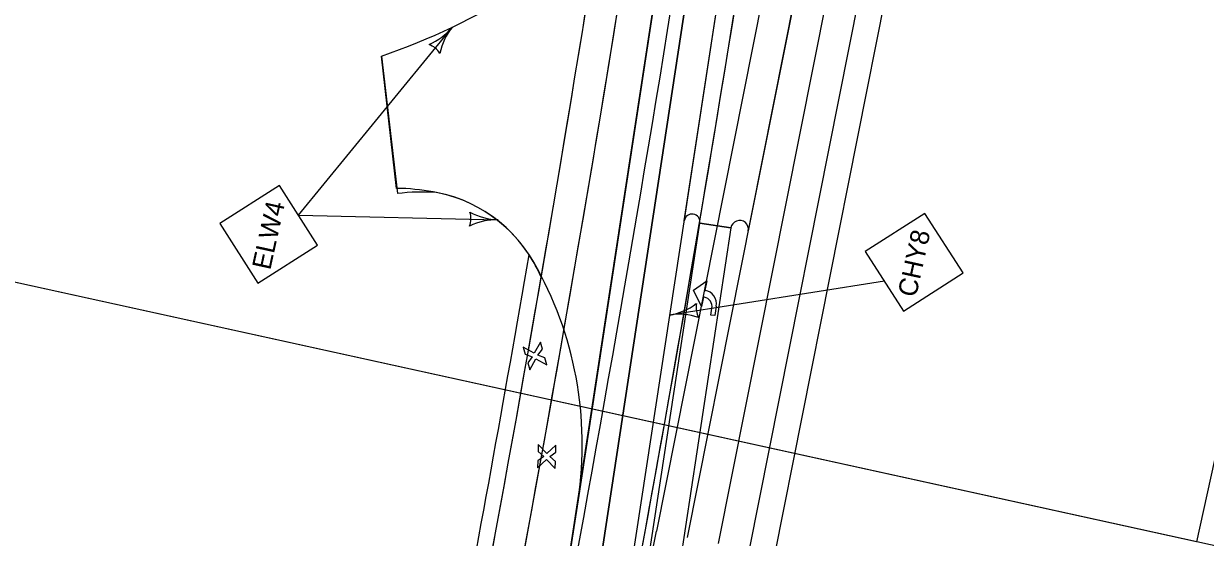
# Model space of a CAD drawing. Extents: x 14104283 to 14128447, y 8633203 to 8671666.
# Drawn here: x 14107697.3 to 14108147.9, y 8639738.3 to 8639934.4 of the extents above; entities that cross this region are included whole.
import ezdxf

# ---------------------------------------------------------------- set-up
doc = ezdxf.new("R2010")
doc.units = 0
for name, color, linetype in [('Cell', 7, 'Continuous'), ('Default', 7, 'Continuous'), ('dsnNonPlotable', 7, 'Continuous'), ('dsnPaintPlaceBrokenLineWhite', 7, 'Continuous'), ('dsnPaintPlaceEdgeLineRightWhite', 7, 'Continuous'), ('dsnStdLabel', 7, 'Continuous'), ('dsnStgShadingPrevPav', 7, 'Continuous')]:
    doc.layers.add(name, color=color, linetype=linetype)

msp = doc.modelspace()

# ---------------------------------------------------------------- linework, layer by layer
at = {"layer": 'Cell'}
for p, q in [((14107957.11, 8639832.53), (14107957.29, 8639832.5)), ((14107956.89, 8639829.91), (14107956.58, 8639829.95)), ((14107894.33, 8639812.75), (14107892.01, 8639808.57)), ((14107895.09, 8639810.1), (14107894.33, 8639812.75)), ((14107892.01, 8639808.57), (14107887.84, 8639810.89)), ((14107887.84, 8639810.89), (14107888.6, 8639808.24)), ((14107888.6, 8639808.24), (14107891.24, 8639807.18)), ((14107893.4, 8639807.8), (14107895.09, 8639810.1)), ((14107891.24, 8639807.18), (14107889.56, 8639804.88)), ((14107889.56, 8639804.88), (14107890.32, 8639802.24)), ((14107890.32, 8639802.24), (14107892.63, 8639806.41)), ((14107892.63, 8639806.41), (14107896.81, 8639804.09)), ((14107896.05, 8639806.74), (14107893.4, 8639807.8)), ((14107896.81, 8639804.09), (14107896.05, 8639806.74)), ((14107893.54, 8639773.76), (14107893.45, 8639771.01)), ((14107896.8, 8639770.27), (14107893.54, 8639773.76)), ((14107900.29, 8639773.53), (14107896.8, 8639770.27)), ((14107900.2, 8639770.79), (14107900.29, 8639773.53)), ((14107893.24, 8639764.76), (14107896.73, 8639768.02)), ((14107895.64, 8639769.19), (14107893.33, 8639767.51)), ((14107893.45, 8639771.01), (14107895.64, 8639769.19)), ((14107896.73, 8639768.02), (14107899.99, 8639764.54)), ((14107897.89, 8639769.11), (14107900.2, 8639770.79)), ((14107900.08, 8639767.29), (14107897.89, 8639769.11)), ((14107893.33, 8639767.51), (14107893.24, 8639764.76)), ((14107899.99, 8639764.54), (14107900.08, 8639767.29))]:
    msp.add_line(p, q, dxfattribs=at)
for points in [[(14107952.78, 8639832.67), (14107957.86, 8639836.14), (14107957.11, 8639832.53)], [(14107952.78, 8639832.67), (14107957.86, 8639836.14), (14107957.11, 8639832.53)], [(14107956.58, 8639829.95), (14107955.83, 8639826.35), (14107952.78, 8639832.67)], [(14107956.58, 8639829.95), (14107955.83, 8639826.35), (14107952.78, 8639832.67)], [(14107957.11, 8639832.53), (14107957.29, 8639832.5)], [(14107956.89, 8639829.91), (14107956.58, 8639829.95)], [(14107961.41, 8639826.54), (14107960.84, 8639822.91), (14107959.37, 8639823.14), (14107959.77, 8639825.73)], [(14107961.41, 8639826.54), (14107960.84, 8639822.91), (14107959.37, 8639823.14), (14107959.77, 8639825.73)]]:
    msp.add_lwpolyline(points, dxfattribs=at)
for centre, major_axis in [((14107956.49, 8639827.31), (-0.81, -5.19)), ((14107956.49, 8639827.31), (-0.81, -5.19)), ((14107956.32, 8639826.27), (-0.57, -3.64)), ((14107956.32, 8639826.27), (-0.57, -3.64))]:
    msp.add_ellipse(centre, major_axis=major_axis, ratio=0.9474, start_param=1.570796, end_param=3.141593, dxfattribs=at)
at = {"layer": 'Default'}
for p, q in [((14107885.37, 8639599.61), (14107990.94, 8640291.61)), ((14108002.8, 8640289.8), (14107897.23, 8639597.8)), ((14108002.8, 8640289.8), (14107897.23, 8639597.8)), ((14107909.09, 8639595.99), (14108014.66, 8640287.99)), ((14108004.96, 8640013.11), (14107973.63, 8639855.23)), ((14108028.5, 8640008.43), (14107973.96, 8639733.6)), ((14107949.24, 8639859.12), (14107967.08, 8639976.1)), ((14107950.42, 8639738.27), (14107992.68, 8639951.24)), ((14107937.44, 8639940.91), (14107908.71, 8639752.63)), ((14107839.51, 8639871.5), (14107833.76, 8639922)), ((14107915.03, 8639595.09), (14107955.17, 8639858.22)), ((14107955.17, 8639858.22), (14107967.03, 8639856.41)), ((14107967.03, 8639856.41), (14107955.17, 8639858.22)), ((14107967.03, 8639856.41), (14107944.41, 8639708.12))]:
    msp.add_line(p, q, dxfattribs=at)
for centre, radius, start, end in [((14107752.7, 8640158.5), 250, 288.9195, 302.3186), ((14107838.11, 8639781.51), 90, 80.198, 89.1076), ((14107844.07, 8639816), 55, 29.809, 80.198), ((14107952.2, 8639858.67), 3, 351.326, 171.326), ((14107970.34, 8639855.88), 3.35, 348.776, 171.0218), ((14107770.31, 8639773.74), 140, 351.326, 29.809)]:
    msp.add_arc(centre, radius, start, end, dxfattribs=at)
at = {"layer": 'dsnNonPlotable'}
for points in [[(14107490.45, 8639880.3), (14107826.84, 8641411.28), (14108813.31, 8641194.53), (14108476.92, 8639663.55)], [(14107651.31, 8639844.94), (14107987.7, 8641375.92), (14108480.93, 8641267.54), (14108144.54, 8639736.56)]]:
    msp.add_lwpolyline(points, close=True, dxfattribs=at)
at = {"layer": 'dsnPaintPlaceBrokenLineWhite'}
msp.add_line((14107897.23, 8639597.8), (14108002.8, 8640289.8), dxfattribs=at)
at = {"layer": 'dsnPaintPlaceEdgeLineRightWhite'}
msp.add_line((14107908.71, 8639752.63), (14107885.37, 8639599.61), dxfattribs=at)
for centre, radius, start, end in [((14107752.7, 8640158.5), 250, 288.9195, 302.3186), ((14107838.11, 8639781.51), 90, 80.198, 89.1076), ((14107844.07, 8639816), 55, 29.809, 80.198), ((14107770.31, 8639773.74), 140, 351.326, 29.809)]:
    msp.add_arc(centre, radius, start, end, dxfattribs=at)
at = {"layer": 'dsnStdLabel'}
for p, q in [((14107802.08, 8639861.24), (14107860.8, 8639933.07)), ((14107802.08, 8639861.24), (14107878.22, 8639859.5)), ((14108025.51, 8639836.03), (14107943.57, 8639823.14))]:
    msp.add_line(p, q, dxfattribs=at)
for points in [[(14107786.61, 8639835.31), (14107809.35, 8639849.86), (14107794.8, 8639872.61), (14107772.06, 8639858.06)], [(14108032.78, 8639824.65), (14108055.53, 8639839.2), (14108040.98, 8639861.95), (14108018.23, 8639847.4)]]:
    msp.add_lwpolyline(points, close=True, dxfattribs=at)
for centre, radius, start, end in [((14107843.03, 8639947.6), 22.95, 292.6641, 320.7354), ((14107878.57, 8639918.55), 22.95, 140.7352, 168.8065), ((14107848.62, 8639918.18), 8.86, 33.0011, 68.4695), ((14107858.98, 8639859.94), 8.86, 340.9615, 16.4299), ((14107878.74, 8639882.45), 22.95, 240.6245, 268.6958), ((14107877.69, 8639836.56), 22.95, 88.6957, 116.7669), ((14107940, 8639845.81), 22.95, 278.9373, 307.0086), ((14107962.58, 8639826.13), 8.86, 171.2032, 206.6716), ((14107947.13, 8639800.47), 22.95, 70.8662, 98.9375)]:
    msp.add_arc(centre, radius, start, end, dxfattribs=at)
at = {"layer": 'dsnStgShadingPrevPav'}
for p, q in [((14107993.19, 8640015.44), (14107938.65, 8639740.6)), ((14107993.19, 8640015.44), (14107938.65, 8639740.6)), ((14107950.42, 8639738.27), (14108004.96, 8640013.11)), ((14108016.73, 8640010.77), (14107962.19, 8639735.93)), ((14108016.73, 8640010.77), (14107962.19, 8639735.93)), ((14107983.77, 8639731.65), (14108038.31, 8640006.49)), ((14107950.42, 8639738.27), (14107992.68, 8639951.24)), ((14107833.76, 8639922), (14107839.82, 8639869.51))]:
    msp.add_line(p, q, dxfattribs=at)
for centre, radius, start, end in [((14098576.76, 8641447.78), 9468, 347.807255, 351.672846), ((14098576.76, 8641447.78), 9456, 348.449343, 351.672846), ((14098576.76, 8641447.78), 9468, 348.194582, 351.672846), ((14098576.76, 8641447.78), 9488, 348.202524, 351.672846), ((14098576.76, 8641447.78), 9488, 348.202524, 351.672846), ((14098576.76, 8641447.78), 9512, 348.176197, 351.653537), ((14098576.76, 8641447.78), 9512, 348.212012, 351.653537), ((14098576.76, 8641447.78), 9456, 350.195701, 351.23682), ((14107752.7, 8640158.5), 250, 288.9195, 302.3186), ((14107849.81, 8639782.85), 87.24, 86.7296, 96.5795), ((14107844.07, 8639816), 55, 23.1027, 78.7566), ((14098576.76, 8641447.78), 9450, 348.220778, 350.242299), ((14107844.07, 8639816), 55, 23.1027, 33.2753), ((14098576.76, 8641447.78), 9456, 348.449343, 350.195701), ((14089678.7, 8643364.11), 18616, 348.014807, 348.776036), ((14089678.7, 8643364.11), 18616, 348.014807, 348.776036)]:
    msp.add_arc(centre, radius, start, end, dxfattribs=at)

# ---------------------------------------------------------------- texts
at = {"layer": 'dsnStdLabel'}
for s, p in [('ELW4', (14107791.33, 8639840.05)), ('CHY8', (14108037.57, 8639829.64))]:
    msp.add_text(s, height=7.2, rotation=77.6078, dxfattribs=at).set_placement(p)

doc.saveas('drawing.dxf')
